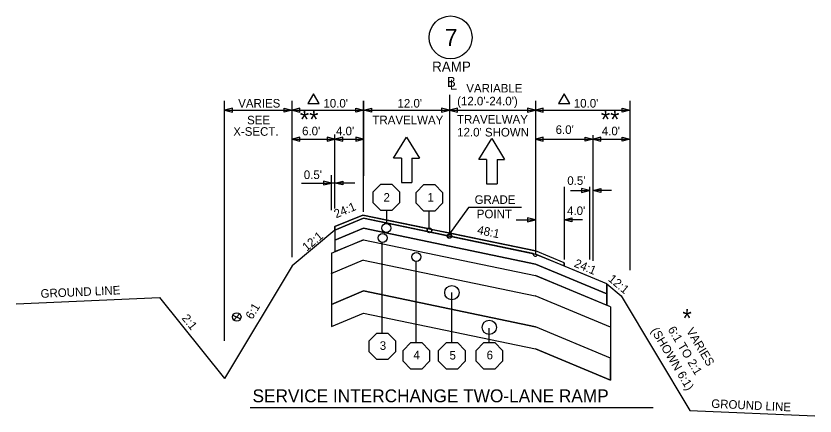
# Model space of a CAD drawing. Extents: x 4932 to 5887, y 4809 to 5473.
# Drawn here: x 5774.1 to 5885.7, y 5068.1 to 5124 of the extents above; entities that cross this region are included whole.
import ezdxf

# ---------------------------------------------------------------- set-up
doc = ezdxf.new("R2010")
doc.units = 0
for name, color, linetype in [('Level 2', 7, 'Continuous'), ('Level 20', 7, 'Continuous'), ('Level 25', 7, 'Continuous'), ('RD_QTY_Intermediate', 7, 'Continuous'), ('RD_QTY_OGFC', 7, 'Continuous'), ('RD_QTY_Surf_Course', 7, 'Continuous'), ('RD_SHT_Typical', 7, 'Continuous'), ('RD_TX_TypSect', 7, 'Continuous'), ('RD_XS_ExGround', 7, 'Continuous'), ('typical_on', 7, 'Continuous')]:
    doc.layers.add(name, color=color, linetype=linetype)

msp = doc.modelspace()

# ---------------------------------------------------------------- linework, layer by layer
at = {"layer": 'Level 2'}
for p, q in [((5818.6, 5091.09), (5818.6, 5091.09)), ((5818.6, 5091.04), (5818.6, 5091.04))]:
    msp.add_line(p, q, dxfattribs=at)
at = {"layer": 'Level 20'}
for p, q in [((5826.81, 5104.17), (5828.63, 5107.08)), ((5828.63, 5107.08), (5830.42, 5104.16)), ((5838.7, 5103.97), (5840.53, 5106.88)), ((5840.53, 5106.88), (5842.31, 5103.96)), ((5827.9, 5104.17), (5826.81, 5104.17)), ((5827.9, 5104.17), (5827.9, 5100.77)), ((5829.36, 5104.16), (5830.42, 5104.16)), ((5829.36, 5104.16), (5829.36, 5100.76)), ((5839.8, 5103.97), (5838.7, 5103.97)), ((5839.8, 5103.97), (5839.8, 5100.57)), ((5841.25, 5103.96), (5842.31, 5103.96)), ((5841.25, 5103.96), (5841.25, 5100.56)), ((5827.9, 5100.77), (5829.36, 5100.76)), ((5839.8, 5100.57), (5841.25, 5100.56))]:
    msp.add_line(p, q, dxfattribs=at)
at = {"layer": 'Level 25'}
for p, q in [((5837.29, 5097.27), (5834.62, 5093.58)), ((5844.68, 5097.27), (5837.29, 5097.27))]:
    msp.add_line(p, q, dxfattribs=at)
msp.add_circle((5834.77, 5121.02), 3, dxfattribs=at)
at = {"layer": 'RD_QTY_Intermediate'}
for p, q in [((5822.62, 5094.35), (5818.62, 5092.69)), ((5846.61, 5089.36), (5822.62, 5094.35)), ((5818.62, 5091.09), (5822.62, 5092.76)), ((5818.62, 5092.69), (5818.62, 5091.09)), ((5822.62, 5092.76), (5846.61, 5087.76)), ((5856.6, 5085.19), (5846.61, 5089.36)), ((5846.61, 5087.76), (5856.6, 5083.6)), ((5856.6, 5083.6), (5856.6, 5085.19))]:
    msp.add_line(p, q, dxfattribs=at)
at = {"layer": 'RD_QTY_OGFC'}
for p, q in [((5822.51, 5096.2), (5818.62, 5094.58)), ((5818.62, 5094.08), (5822.62, 5095.75)), ((5831.6, 5094.31), (5822.51, 5096.2)), ((5822.62, 5095.75), (5831.52, 5093.9)), ((5818.62, 5094.58), (5818.62, 5094.08))]:
    msp.add_line(p, q, dxfattribs=at)
msp.add_arc((5831.81, 5094.05), 0.332, 129.1992, 207.7584, dxfattribs=at)
at = {"layer": 'RD_QTY_Surf_Course'}
for p, q in [((5822.62, 5095.75), (5818.62, 5094.08)), ((5846.31, 5090.81), (5822.62, 5095.75)), ((5818.62, 5092.69), (5822.62, 5094.35)), ((5822.62, 5094.35), (5846.61, 5089.36)), ((5818.62, 5094.08), (5818.62, 5092.69)), ((5856.6, 5086.57), (5846.88, 5090.64)), ((5846.61, 5089.36), (5856.6, 5085.19)), ((5856.6, 5085.19), (5856.6, 5086.57))]:
    msp.add_line(p, q, dxfattribs=at)
msp.add_circle((5825.8, 5094.39), 0.63, dxfattribs=at)
msp.add_arc((5846.61, 5090.75), 0.3, 168.2319, 337.3117, dxfattribs=at)
at = {"layer": 'RD_SHT_Typical'}
for p, q in [((5818.62, 5094.58), (5822.51, 5096.2)), ((5818.62, 5094.08), (5822.62, 5095.75)), ((5818.62, 5094.08), (5818.62, 5094.58)), ((5818.62, 5092.69), (5822.62, 5094.35)), ((5834.93, 5093.61), (5832.1, 5094.2)), ((5818.62, 5094.08), (5812.62, 5089.09)), ((5818.62, 5094.08), (5818.62, 5091.09)), ((5832.02, 5093.79), (5834.32, 5093.31)), ((5834.8, 5093.48), (5834.93, 5093.61)), ((5834.93, 5093.61), (5834.8, 5093.48)), ((5834.91, 5093.19), (5846.31, 5090.81)), ((5846.61, 5091.18), (5834.93, 5093.61)), ((5818.12, 5090.88), (5822.64, 5092.77)), ((5818.12, 5090.88), (5818.12, 5080.63)), ((5850.61, 5089.51), (5846.61, 5091.18)), ((5850.61, 5089.51), (5846.61, 5091.18)), ((5818.09, 5088.05), (5822.61, 5089.93)), ((5846.31, 5090.81), (5846.61, 5090.75)), ((5856.6, 5086.59), (5846.61, 5090.75)), ((5812.62, 5089.09), (5803.18, 5073.35)), ((5856.6, 5085.19), (5846.61, 5089.36)), ((5850.61, 5089.51), (5850.61, 5089.09)), ((5850.61, 5089.09), (5850.61, 5089.51)), ((5857.1, 5083.39), (5846.61, 5087.76)), ((5856.6, 5086.59), (5858.6, 5084.91)), ((5856.6, 5086.57), (5856.6, 5083.6)), ((5818.12, 5083.72), (5822.62, 5085.6)), ((5794.09, 5084.7), (5803.18, 5073.35)), ((5857.1, 5080.54), (5846.58, 5084.92)), ((5858.6, 5084.91), (5868.2, 5068.91)), ((5857.1, 5083.39), (5857.1, 5073.12)), ((5818.12, 5080.63), (5822.61, 5082.5)), ((5857.1, 5076.21), (5846.61, 5080.59)), ((5857.1, 5073.12), (5846.61, 5077.49))]:
    msp.add_line(p, q, dxfattribs=at)
for points in [[(5822.51, 5096.2), (5846.61, 5091.18)], [(5822.62, 5095.75), (5846.61, 5090.75)], [(5822.62, 5094.35), (5846.61, 5089.36)], [(5834.8, 5093.48), (5834.8, 5093.48)], [(5822.62, 5092.76), (5846.61, 5087.76)], [(5822.59, 5089.92), (5846.58, 5084.92)], [(5846.61, 5090.75), (5846.88, 5090.64), (5850.61, 5089.09)], [(5850.61, 5089.09), (5850.61, 5089.09)], [(5822.59, 5085.59), (5846.61, 5080.59)], [(5822.59, 5082.49), (5846.61, 5077.49)]]:
    msp.add_lwpolyline(points, dxfattribs=at)
for centre, radius, start, end in [((5831.81, 5094.05), 0.332, 308.7054, 27.2647), ((5834.61, 5093.25), 0.3, 50.3383, 168.2319), ((5834.61, 5093.25), 0.3, 348.2319, 50.3383)]:
    msp.add_arc(centre, radius, start, end, dxfattribs=at)
at = {"layer": 'RD_TX_TypSect'}
for p, q in [((5803.18, 5078.63), (5803.18, 5112.18)), ((5812.62, 5090.33), (5812.62, 5112.18)), ((5822.62, 5096.66), (5822.62, 5112.18)), ((5822.62, 5112.15), (5822.62, 5101.69)), ((5834.61, 5113.02), (5834.61, 5093.8)), ((5846.61, 5112.15), (5846.61, 5090.75)), ((5859.82, 5112.15), (5859.82, 5088.5)), ((5803.18, 5110.86), (5812.62, 5110.86)), ((5812.62, 5110.86), (5822.62, 5110.86)), ((5822.62, 5110.86), (5834.61, 5110.86)), ((5834.61, 5110.86), (5846.61, 5110.86)), ((5846.61, 5110.86), (5859.82, 5110.86)), ((5812.62, 5106.82), (5818.62, 5106.82)), ((5818.62, 5097.12), (5818.62, 5107.44)), ((5818.62, 5106.82), (5822.62, 5106.82)), ((5846.61, 5106.82), (5854.66, 5106.82)), ((5854.66, 5089.8), (5854.66, 5107.35)), ((5854.66, 5106.82), (5859.82, 5106.82)), ((5818.12, 5096.89), (5818.12, 5101.76)), ((5813.94, 5100.68), (5818.12, 5100.68)), ((5821.38, 5100.68), (5818.12, 5100.68)), ((5850.61, 5100.15), (5850.61, 5090)), ((5854.17, 5100.15), (5854.17, 5090)), ((5851.51, 5099.62), (5854.17, 5099.62)), ((5857.24, 5099.62), (5854.66, 5099.62)), ((5825.8, 5096.82), (5825.8, 5095.02)), ((5831.79, 5094.38), (5831.79, 5096.76)), ((5843.95, 5095.55), (5846.61, 5095.55)), ((5853.18, 5095.55), (5850.61, 5095.55)), ((5825.22, 5079.7), (5825.22, 5092.39)), ((5829.96, 5078.37), (5829.96, 5089.73)), ((5846.61, 5080.59), (5822.6, 5085.59)), ((5834.93, 5078.37), (5834.93, 5085.38)), ((5818.12, 5083.72), (5818.12, 5080.63)), ((5804.35, 5082.23), (5805.42, 5081.68)), ((5804.47, 5081.53), (5805.3, 5082.38)), ((5818.12, 5080.63), (5822.59, 5082.49)), ((5822.59, 5082.49), (5846.61, 5077.49)), ((5840.17, 5078.37), (5840.17, 5080.41)), ((5857.1, 5076.21), (5846.61, 5080.59)), ((5846.61, 5077.49), (5857.1, 5073.12)), ((5857.1, 5073.12), (5857.1, 5076.21)), ((5806.77, 5069.33), (5863.08, 5069.33))]:
    msp.add_line(p, q, dxfattribs=at)
for points in [[(5815.62, 5113.15), (5814.82, 5111.77), (5816.42, 5111.77)], [(5850.63, 5113.15), (5849.83, 5111.77), (5851.43, 5111.77)], [(5804.28, 5110.58), (5804.28, 5111.13), (5803.18, 5110.86)], [(5811.52, 5110.58), (5811.52, 5111.13), (5812.62, 5110.86)], [(5813.72, 5110.58), (5813.72, 5111.13), (5812.62, 5110.86)], [(5821.51, 5110.58), (5821.51, 5111.13), (5822.62, 5110.86)], [(5823.72, 5111.13), (5823.72, 5110.58), (5822.62, 5110.86)], [(5833.51, 5111.13), (5833.51, 5110.58), (5834.61, 5110.86)], [(5835.72, 5110.58), (5835.72, 5111.13), (5834.61, 5110.86)], [(5845.5, 5111.13), (5845.5, 5110.58), (5846.61, 5110.86)], [(5847.71, 5110.58), (5847.71, 5111.13), (5846.61, 5110.86)], [(5858.72, 5110.58), (5858.72, 5111.13), (5859.82, 5110.86)], [(5813.72, 5106.54), (5813.72, 5107.09), (5812.62, 5106.82)], [(5817.52, 5107.09), (5817.52, 5106.54), (5818.62, 5106.82)], [(5819.72, 5106.54), (5819.72, 5107.09), (5818.62, 5106.82)], [(5821.51, 5107.09), (5821.51, 5106.54), (5822.62, 5106.82)], [(5847.71, 5106.54), (5847.71, 5107.09), (5846.61, 5106.82)], [(5853.56, 5106.54), (5853.56, 5107.09), (5854.66, 5106.82)], [(5855.77, 5106.54), (5855.77, 5107.09), (5854.66, 5106.82)], [(5858.72, 5106.54), (5858.72, 5107.09), (5859.82, 5106.82)], [(5817.02, 5100.96), (5817.02, 5100.41), (5818.12, 5100.68)], [(5819.72, 5100.96), (5819.72, 5100.41), (5818.62, 5100.68)], [(5853.06, 5099.89), (5853.06, 5099.34), (5854.17, 5099.62)], [(5855.77, 5099.89), (5855.77, 5099.34), (5854.66, 5099.62)], [(5845.5, 5095.82), (5845.5, 5095.27), (5846.61, 5095.55)], [(5851.71, 5095.82), (5851.71, 5095.27), (5850.61, 5095.55)]]:
    msp.add_lwpolyline(points, close=True, dxfattribs=at)
msp.add_lwpolyline([(5822.6, 5085.59), (5822.59, 5085.59), (5818.12, 5083.72)], dxfattribs=at)
for centre, radius in [((5825.8, 5094.39), 0.63), ((5831.81, 5094.05), 0.332), ((5825.26, 5093.01), 0.63), ((5834.61, 5093.25), 0.3), ((5834.62, 5093.28), 0.3), ((5829.98, 5090.36), 0.63), ((5834.95, 5085.36), 1), ((5804.89, 5081.96), 0.6), ((5840.17, 5080.51), 1), ((5840.17, 5080.51), 1)]:
    msp.add_circle(centre, radius, dxfattribs=at)
at = {"layer": 'RD_XS_ExGround'}
for p, q in [((5774.06, 5083.79), (5794.09, 5084.7)), ((5868.2, 5068.91), (5885.67, 5068.12))]:
    msp.add_line(p, q, dxfattribs=at)
at = {"layer": 'typical_on'}
for points in [[(5827.64, 5099.43), (5827.64, 5097.9), (5826.56, 5096.82), (5825.03, 5096.82), (5823.95, 5097.9), (5823.95, 5099.43), (5825.03, 5100.51), (5826.56, 5100.51)], [(5833.64, 5099.37), (5833.64, 5097.84), (5832.56, 5096.76), (5831.03, 5096.76), (5829.95, 5097.84), (5829.95, 5099.37), (5831.03, 5100.45), (5832.56, 5100.45)], [(5827.09, 5078.62), (5827.09, 5077.09), (5826.01, 5076.01), (5824.48, 5076.01), (5823.39, 5077.09), (5823.39, 5078.62), (5824.48, 5079.7), (5826.01, 5079.7)], [(5831.83, 5077.29), (5831.83, 5075.76), (5830.74, 5074.68), (5829.22, 5074.68), (5828.13, 5075.76), (5828.13, 5077.29), (5829.22, 5078.37), (5830.74, 5078.37)], [(5836.79, 5077.29), (5836.79, 5075.76), (5835.71, 5074.68), (5834.18, 5074.68), (5833.1, 5075.76), (5833.1, 5077.29), (5834.18, 5078.37), (5835.71, 5078.37)], [(5842.03, 5077.29), (5842.03, 5075.76), (5840.95, 5074.68), (5839.42, 5074.68), (5838.34, 5075.76), (5838.34, 5077.29), (5839.42, 5078.37), (5840.95, 5078.37)]]:
    msp.add_lwpolyline(points, close=True, dxfattribs=at)

# ---------------------------------------------------------------- texts
at = {"layer": 'Level 25'}
msp.add_text('7', height=2.4, dxfattribs=at).set_placement((5833.95, 5119.82))
at = {"layer": 'RD_TX_TypSect'}
for s, height, p in [('RAMP', 1.4, (5832.19, 5116.25)), ('B ', 1.4, (5834.24, 5114.11)), ('L', 1.4, (5834.65, 5113.72)), ('VARIES', 1.2, (5805.1, 5111.22)), ("10.0'", 1.2, (5817, 5111.22)), ("12.0'", 1.2, (5827.35, 5111.22)), ("10.0'", 1.2, (5851.98, 5111.22)), ('SEE', 1.2, (5806.34, 5108.88)), ('**', 2.5, (5813.71, 5108.33)), ('TRAVELWAY', 1.2, (5823.85, 5108.89)), ('**', 2.5, (5855.76, 5108.33)), ("6.0'", 1.2, (5849.44, 5107.54)), ('X-SECT.', 1.2, (5804.41, 5107.28)), ("6.0'", 1.2, (5814.02, 5107.35)), ("4.0'", 1.2, (5818.76, 5107.35)), ("4.0'", 1.2, (5855.89, 5107.35)), ("0.5'", 1.2, (5814.26, 5101.24)), ("0.5'", 1.2, (5851.07, 5100.42)), ('2', 1.2, (5825.4, 5098.07)), ('1', 1.2, (5831.54, 5098.09)), ('GRADE', 1.2, (5838.12, 5097.76)), ('POINT', 1.2, (5838.43, 5095.76)), ("4.0'", 1.2, (5851.04, 5096.21)), ('*', 2.5, (5867.15, 5080.55)), ('3', 1.2, (5824.87, 5077.36)), ('4', 1.2, (5829.58, 5076.06)), ('5', 1.2, (5834.61, 5076.01)), ('6', 1.2, (5839.8, 5076.04)), ('SERVICE INTERCHANGE TWO-LANE RAMP', 1.8, (5807.1, 5070.04))]:
    msp.add_text(s, height=height, dxfattribs=at).set_placement(p)
for s, rotation, p in [('VARIABLE', 0.0016, (5836.96, 5113.33)), ("(12.0'-24.0')", 0.0016, (5835.68, 5111.53)), ('TRAVELWAY', 0.0016, (5835.67, 5108.98)), ("12.0' SHOWN", 0.0016, (5835.69, 5107.18)), ('24:1', 22.619, (5818.78, 5095.74)), ('48:1', 348.2317, (5838.42, 5093.59)), ('12:1', 39.8056, (5814.67, 5091.08)), ('24:1', 337.3801, (5851.92, 5089.02)), ('12:1', 320.1939, (5856.68, 5087.1)), ('GROUND LINE', 2.6095, (5777.52, 5084.62)), ('6:1', 59.0362, (5807.06, 5081.52)), ('2:1', 308.6598, (5797.15, 5081.76)), ('(SHOWN 6:1)', 300.9638, (5862.71, 5080.06)), ('6:1 TO 2:1', 300.9638, (5865.06, 5080.22)), ('VARIES', 300.9638, (5867.64, 5080.01)), ('GROUND LINE', 357.3905, (5871.16, 5069.27))]:
    msp.add_text(s, height=1.2, rotation=rotation, dxfattribs=at).set_placement(p)

doc.saveas('drawing.dxf')
